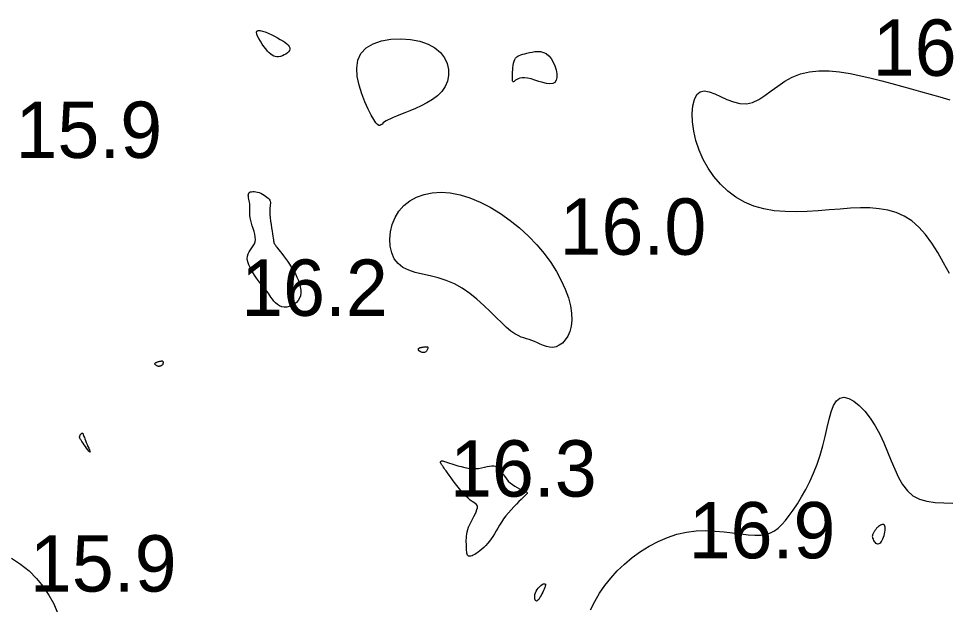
# Model space of a CAD drawing. Extents: x 3040093 to 3056816, y 408076 to 509144.
# Drawn here: x 3045513.5 to 3045596, y 434343.4 to 434395.4 of the extents above; entities that cross this region are included whole.
import ezdxf

# ---------------------------------------------------------------- set-up
doc = ezdxf.new("R2010")
doc.units = 0
doc.layers.add('V-CHAN-CONT-EL17', color=7, linetype='Continuous')
doc.layers.add('V-TOPO-SOUN-0610', color=7, linetype='Continuous')

msp = doc.modelspace()

# ---------------------------------------------------------------- linework, layer by layer
at = {"layer": 'V-CHAN-CONT-EL17'}
for points in [[(3045534.704, 434394.312), (3045534.867, 434394.31), (3045535.076, 434394.265), (3045535.321, 434394.183), (3045535.589, 434394.074), (3045535.868, 434393.946), (3045536.149, 434393.807), (3045536.418, 434393.664), (3045536.666, 434393.525), (3045536.889, 434393.391), (3045537.083, 434393.261), (3045537.246, 434393.134), (3045537.374, 434393.01), (3045537.464, 434392.889), (3045537.515, 434392.77), (3045537.521, 434392.652), (3045537.483, 434392.536), (3045537.405, 434392.423), (3045537.296, 434392.317), (3045537.161, 434392.221), (3045537.009, 434392.136), (3045536.847, 434392.067), (3045536.681, 434392.016), (3045536.52, 434391.986), (3045536.368, 434391.98), (3045536.224, 434391.998), (3045536.086, 434392.041), (3045535.951, 434392.111), (3045535.816, 434392.208), (3045535.677, 434392.332), (3045535.532, 434392.486), (3045535.379, 434392.669), (3045535.216, 434392.881), (3045535.051, 434393.111), (3045534.895, 434393.35), (3045534.758, 434393.585), (3045534.65, 434393.804), (3045534.58, 434393.998), (3045534.56, 434394.154), (3045534.599, 434394.262)], [(3045544.269, 434392.762), (3045544.898, 434393.134), (3045545.651, 434393.391), (3045546.484, 434393.539), (3045547.355, 434393.58), (3045548.223, 434393.519), (3045549.044, 434393.36), (3045549.776, 434393.106), (3045550.385, 434392.765), (3045550.866, 434392.35), (3045551.224, 434391.881), (3045551.461, 434391.374), (3045551.583, 434390.848), (3045551.592, 434390.321), (3045551.492, 434389.809), (3045551.288, 434389.331), (3045550.985, 434388.9), (3045550.601, 434388.518), (3045550.155, 434388.179), (3045549.669, 434387.88), (3045549.162, 434387.618), (3045548.654, 434387.387), (3045548.165, 434387.186), (3045547.716, 434387.01), (3045547.321, 434386.855), (3045546.981, 434386.718), (3045546.691, 434386.596), (3045546.444, 434386.486), (3045546.236, 434386.385), (3045546.062, 434386.289), (3045545.917, 434386.196), (3045545.796, 434386.102), (3045545.692, 434386.009), (3045545.598, 434385.93), (3045545.504, 434385.885), (3045545.403, 434385.891), (3045545.283, 434385.966), (3045545.138, 434386.131), (3045544.956, 434386.401), (3045544.731, 434386.797), (3045544.459, 434387.328), (3045544.167, 434387.969), (3045543.886, 434388.687), (3045543.65, 434389.449), (3045543.491, 434390.222), (3045543.442, 434390.972), (3045543.536, 434391.666), (3045543.805, 434392.272)], [(3045557.354, 434389.768), (3045557.318, 434389.766), (3045557.292, 434389.787), (3045557.276, 434389.832), (3045557.266, 434389.901), (3045557.262, 434389.994), (3045557.262, 434390.113), (3045557.265, 434390.257), (3045557.269, 434390.426), (3045557.275, 434390.613), (3045557.286, 434390.812), (3045557.303, 434391.016), (3045557.328, 434391.218), (3045557.363, 434391.411), (3045557.41, 434391.586), (3045557.47, 434391.739), (3045557.544, 434391.863), (3045557.635, 434391.961), (3045557.742, 434392.039), (3045557.866, 434392.101), (3045558.009, 434392.152), (3045558.17, 434392.197), (3045558.35, 434392.241), (3045558.551, 434392.289), (3045558.771, 434392.343), (3045559.008, 434392.395), (3045559.255, 434392.434), (3045559.509, 434392.451), (3045559.763, 434392.433), (3045560.014, 434392.371), (3045560.256, 434392.254), (3045560.484, 434392.072), (3045560.693, 434391.818), (3045560.875, 434391.509), (3045561.025, 434391.167), (3045561.135, 434390.812), (3045561.197, 434390.467), (3045561.205, 434390.152), (3045561.151, 434389.89), (3045561.028, 434389.701), (3045560.833, 434389.6), (3045560.577, 434389.576), (3045560.275, 434389.613), (3045559.942, 434389.692), (3045559.593, 434389.796), (3045559.244, 434389.907), (3045558.909, 434390.008), (3045558.603, 434390.082), (3045558.338, 434390.115), (3045558.113, 434390.111), (3045557.926, 434390.08), (3045557.771, 434390.028), (3045557.645, 434389.965), (3045557.544, 434389.9), (3045557.464, 434389.839), (3045557.402, 434389.793)], [(3045534.743, 434372.083), (3045534.56, 434372.335), (3045534.372, 434372.613), (3045534.189, 434372.906), (3045534.023, 434373.206), (3045533.886, 434373.502), (3045533.788, 434373.785), (3045533.741, 434374.046), (3045533.753, 434374.278), (3045533.813, 434374.485), (3045533.909, 434374.673), (3045534.027, 434374.849), (3045534.152, 434375.02), (3045534.271, 434375.191), (3045534.371, 434375.37), (3045534.437, 434375.563), (3045534.46, 434375.774), (3045534.446, 434376.001), (3045534.401, 434376.241), (3045534.336, 434376.487), (3045534.258, 434376.737), (3045534.178, 434376.985), (3045534.102, 434377.228), (3045534.04, 434377.46), (3045533.999, 434377.678), (3045533.976, 434377.884), (3045533.967, 434378.077), (3045533.967, 434378.26), (3045533.971, 434378.434), (3045533.976, 434378.6), (3045533.976, 434378.76), (3045533.968, 434378.914), (3045533.947, 434379.065), (3045533.919, 434379.209), (3045533.887, 434379.347), (3045533.857, 434379.476), (3045533.835, 434379.595), (3045533.825, 434379.702), (3045533.832, 434379.795), (3045533.862, 434379.873), (3045533.919, 434379.934), (3045534, 434379.979), (3045534.101, 434380.008), (3045534.22, 434380.021), (3045534.352, 434380.019), (3045534.494, 434380.001), (3045534.643, 434379.969), (3045534.795, 434379.923), (3045534.946, 434379.863), (3045535.094, 434379.791), (3045535.236, 434379.71), (3045535.367, 434379.621), (3045535.485, 434379.528), (3045535.588, 434379.432), (3045535.671, 434379.337), (3045535.732, 434379.243), (3045535.768, 434379.152), (3045535.785, 434379.06), (3045535.786, 434378.962), (3045535.776, 434378.853), (3045535.762, 434378.726), (3045535.747, 434378.578), (3045535.736, 434378.401), (3045535.736, 434378.192), (3045535.749, 434377.947), (3045535.774, 434377.674), (3045535.808, 434377.384), (3045535.848, 434377.087), (3045535.891, 434376.795), (3045535.934, 434376.517), (3045535.974, 434376.264), (3045536.009, 434376.047), (3045536.036, 434375.874), (3045536.057, 434375.74), (3045536.072, 434375.64), (3045536.084, 434375.566), (3045536.094, 434375.512), (3045536.105, 434375.472), (3045536.118, 434375.438), (3045536.135, 434375.405), (3045536.157, 434375.366), (3045536.187, 434375.318), (3045536.227, 434375.258), (3045536.278, 434375.184), (3045536.344, 434375.094), (3045536.426, 434374.984), (3045536.527, 434374.852), (3045536.647, 434374.696), (3045536.79, 434374.513), (3045536.95, 434374.306), (3045537.122, 434374.078), (3045537.302, 434373.831), (3045537.485, 434373.569), (3045537.666, 434373.294), (3045537.84, 434373.01), (3045538.001, 434372.72), (3045538.146, 434372.426), (3045538.269, 434372.131), (3045538.369, 434371.84), (3045538.44, 434371.555), (3045538.48, 434371.28), (3045538.484, 434371.018), (3045538.449, 434370.773), (3045538.372, 434370.547), (3045538.251, 434370.344), (3045538.092, 434370.167), (3045537.903, 434370.019), (3045537.692, 434369.902), (3045537.467, 434369.819), (3045537.236, 434369.773), (3045537.008, 434369.766), (3045536.791, 434369.802), (3045536.591, 434369.881), (3045536.408, 434369.996), (3045536.243, 434370.138), (3045536.094, 434370.298), (3045535.96, 434370.467), (3045535.841, 434370.636), (3045535.735, 434370.795), (3045535.643, 434370.937), (3045535.562, 434371.055), (3045535.488, 434371.154), (3045535.417, 434371.244), (3045535.342, 434371.333), (3045535.258, 434371.431), (3045535.162, 434371.546), (3045535.047, 434371.688), (3045534.908, 434371.865)], [(3045551.393, 434372.133), (3045550.675, 434372.357), (3045549.967, 434372.533), (3045549.284, 434372.687), (3045548.642, 434372.847), (3045548.055, 434373.038), (3045547.54, 434373.287), (3045547.11, 434373.621), (3045546.778, 434374.058), (3045546.546, 434374.582), (3045546.413, 434375.172), (3045546.377, 434375.803), (3045546.439, 434376.453), (3045546.597, 434377.098), (3045546.849, 434377.715), (3045547.195, 434378.28), (3045547.633, 434378.774), (3045548.155, 434379.189), (3045548.754, 434379.519), (3045549.421, 434379.76), (3045550.148, 434379.908), (3045550.927, 434379.957), (3045551.75, 434379.902), (3045552.608, 434379.739), (3045553.493, 434379.466), (3045554.393, 434379.091), (3045555.296, 434378.624), (3045556.188, 434378.077), (3045557.058, 434377.461), (3045557.894, 434376.786), (3045558.682, 434376.064), (3045559.411, 434375.305), (3045560.07, 434374.521), (3045560.655, 434373.722), (3045561.164, 434372.919), (3045561.596, 434372.123), (3045561.948, 434371.345), (3045562.219, 434370.594), (3045562.407, 434369.883), (3045562.509, 434369.222), (3045562.527, 434368.619), (3045562.468, 434368.079), (3045562.344, 434367.603), (3045562.166, 434367.194), (3045561.945, 434366.852), (3045561.692, 434366.579), (3045561.417, 434366.378), (3045561.132, 434366.25), (3045560.845, 434366.195), (3045560.561, 434366.201), (3045560.28, 434366.257), (3045560.004, 434366.348), (3045559.734, 434366.462), (3045559.472, 434366.586), (3045559.219, 434366.706), (3045558.975, 434366.811), (3045558.743, 434366.89), (3045558.513, 434366.956), (3045558.279, 434367.024), (3045558.032, 434367.111), (3045557.763, 434367.231), (3045557.465, 434367.4), (3045557.129, 434367.635), (3045556.747, 434367.951), (3045556.312, 434368.357), (3045555.827, 434368.836), (3045555.296, 434369.362), (3045554.724, 434369.91), (3045554.115, 434370.456), (3045553.472, 434370.976), (3045552.801, 434371.443), (3045552.106, 434371.835)], [(3045548.943, 434365.924), (3045548.933, 434365.942), (3045548.925, 434365.961), (3045548.919, 434365.981), (3045548.915, 434366.001), (3045548.914, 434366.021), (3045548.917, 434366.042), (3045548.923, 434366.061), (3045548.933, 434366.08), (3045548.947, 434366.097), (3045548.964, 434366.114), (3045548.983, 434366.129), (3045549.005, 434366.142), (3045549.028, 434366.154), (3045549.052, 434366.165), (3045549.077, 434366.173), (3045549.102, 434366.18), (3045549.127, 434366.186), (3045549.154, 434366.19), (3045549.184, 434366.194), (3045549.218, 434366.199), (3045549.255, 434366.204), (3045549.298, 434366.211), (3045549.347, 434366.219), (3045549.403, 434366.23), (3045549.462, 434366.24), (3045549.523, 434366.249), (3045549.582, 434366.254), (3045549.637, 434366.254), (3045549.684, 434366.245), (3045549.722, 434366.227), (3045549.746, 434366.196), (3045549.754, 434366.153), (3045549.749, 434366.099), (3045549.731, 434366.039), (3045549.703, 434365.975), (3045549.666, 434365.912), (3045549.622, 434365.853), (3045549.574, 434365.802), (3045549.521, 434365.762), (3045549.467, 434365.737), (3045549.413, 434365.725), (3045549.359, 434365.723), (3045549.306, 434365.73), (3045549.255, 434365.743), (3045549.207, 434365.76), (3045549.163, 434365.779), (3045549.123, 434365.798), (3045549.089, 434365.815), (3045549.059, 434365.829), (3045549.034, 434365.843), (3045549.013, 434365.855), (3045548.995, 434365.867), (3045548.98, 434365.88), (3045548.966, 434365.893), (3045548.954, 434365.907)], [(3045525.758, 434364.538), (3045525.714, 434364.559), (3045525.671, 434364.584), (3045525.63, 434364.611), (3045525.595, 434364.641), (3045525.566, 434364.671), (3045525.547, 434364.702), (3045525.541, 434364.732), (3045525.547, 434364.761), (3045525.566, 434364.788), (3045525.594, 434364.813), (3045525.63, 434364.836), (3045525.672, 434364.858), (3045525.718, 434364.878), (3045525.764, 434364.895), (3045525.81, 434364.911), (3045525.853, 434364.925), (3045525.893, 434364.937), (3045525.931, 434364.948), (3045525.966, 434364.957), (3045525.999, 434364.964), (3045526.029, 434364.97), (3045526.058, 434364.975), (3045526.085, 434364.979), (3045526.11, 434364.983), (3045526.134, 434364.985), (3045526.156, 434364.986), (3045526.175, 434364.986), (3045526.193, 434364.984), (3045526.209, 434364.98), (3045526.223, 434364.975), (3045526.234, 434364.968), (3045526.243, 434364.959), (3045526.25, 434364.947), (3045526.255, 434364.934), (3045526.258, 434364.919), (3045526.26, 434364.902), (3045526.262, 434364.884), (3045526.262, 434364.864), (3045526.262, 434364.843), (3045526.262, 434364.821), (3045526.261, 434364.798), (3045526.259, 434364.774), (3045526.255, 434364.751), (3045526.25, 434364.727), (3045526.243, 434364.704), (3045526.233, 434364.682), (3045526.22, 434364.661), (3045526.204, 434364.641), (3045526.185, 434364.623), (3045526.164, 434364.606), (3045526.141, 434364.59), (3045526.116, 434364.576), (3045526.091, 434364.562), (3045526.065, 434364.55), (3045526.039, 434364.538), (3045526.014, 434364.527), (3045525.988, 434364.518), (3045525.962, 434364.51), (3045525.934, 434364.505), (3045525.905, 434364.503), (3045525.873, 434364.505), (3045525.838, 434364.511), (3045525.8, 434364.522)], [(3045518.863, 434358.237), (3045518.866, 434358.257), (3045518.87, 434358.278), (3045518.876, 434358.302), (3045518.884, 434358.329), (3045518.895, 434358.357), (3045518.908, 434358.387), (3045518.925, 434358.419), (3045518.945, 434358.453), (3045518.968, 434358.487), (3045518.993, 434358.518), (3045519.019, 434358.546), (3045519.046, 434358.567), (3045519.073, 434358.579), (3045519.099, 434358.582), (3045519.123, 434358.572), (3045519.145, 434358.548), (3045519.167, 434358.509), (3045519.19, 434358.454), (3045519.216, 434358.382), (3045519.247, 434358.294), (3045519.285, 434358.187), (3045519.332, 434358.062), (3045519.388, 434357.917), (3045519.456, 434357.754), (3045519.53, 434357.581), (3045519.605, 434357.407), (3045519.674, 434357.243), (3045519.733, 434357.098), (3045519.775, 434356.983), (3045519.794, 434356.907), (3045519.785, 434356.88), (3045519.745, 434356.908), (3045519.677, 434356.985), (3045519.588, 434357.098), (3045519.486, 434357.237), (3045519.377, 434357.392), (3045519.267, 434357.55), (3045519.164, 434357.702), (3045519.074, 434357.836), (3045519.003, 434357.944), (3045518.949, 434358.027), (3045518.911, 434358.089), (3045518.885, 434358.133), (3045518.869, 434358.165), (3045518.862, 434358.187), (3045518.86, 434358.204), (3045518.861, 434358.22)], [(3045553.251, 434347.839), (3045553.227, 434347.932), (3045553.21, 434348.04), (3045553.197, 434348.163), (3045553.188, 434348.296), (3045553.182, 434348.44), (3045553.177, 434348.591), (3045553.173, 434348.748), (3045553.169, 434348.91), (3045553.167, 434349.077), (3045553.17, 434349.25), (3045553.182, 434349.43), (3045553.205, 434349.618), (3045553.243, 434349.816), (3045553.298, 434350.024), (3045553.374, 434350.243), (3045553.471, 434350.474), (3045553.584, 434350.711), (3045553.705, 434350.949), (3045553.826, 434351.182), (3045553.94, 434351.404), (3045554.037, 434351.61), (3045554.111, 434351.792), (3045554.154, 434351.946), (3045554.16, 434352.068), (3045554.129, 434352.166), (3045554.064, 434352.249), (3045553.968, 434352.327), (3045553.844, 434352.412), (3045553.694, 434352.512), (3045553.521, 434352.637), (3045553.328, 434352.799), (3045553.118, 434353.002), (3045552.897, 434353.241), (3045552.669, 434353.505), (3045552.44, 434353.785), (3045552.217, 434354.069), (3045552.005, 434354.348), (3045551.81, 434354.611), (3045551.637, 434354.848), (3045551.491, 434355.052), (3045551.369, 434355.223), (3045551.27, 434355.366), (3045551.19, 434355.482), (3045551.126, 434355.578), (3045551.076, 434355.655), (3045551.035, 434355.717), (3045551.002, 434355.768), (3045550.973, 434355.811), (3045550.948, 434355.848), (3045550.927, 434355.879), (3045550.91, 434355.905), (3045550.897, 434355.929), (3045550.888, 434355.95), (3045550.882, 434355.97), (3045550.881, 434355.989), (3045550.882, 434356.009), (3045550.887, 434356.03), (3045550.896, 434356.05), (3045550.907, 434356.069), (3045550.922, 434356.086), (3045550.94, 434356.101), (3045550.96, 434356.113), (3045550.983, 434356.121), (3045551.01, 434356.125), (3045551.044, 434356.123), (3045551.09, 434356.115), (3045551.153, 434356.099), (3045551.237, 434356.073), (3045551.349, 434356.037), (3045551.492, 434355.99), (3045551.671, 434355.93), (3045551.889, 434355.856), (3045552.141, 434355.775), (3045552.42, 434355.69), (3045552.718, 434355.61), (3045553.028, 434355.538), (3045553.344, 434355.481), (3045553.657, 434355.445), (3045553.96, 434355.436), (3045554.248, 434355.456), (3045554.519, 434355.499), (3045554.773, 434355.553), (3045555.009, 434355.61), (3045555.229, 434355.658), (3045555.43, 434355.688), (3045555.614, 434355.689), (3045555.781, 434355.652), (3045555.93, 434355.569), (3045556.066, 434355.446), (3045556.194, 434355.291), (3045556.319, 434355.112), (3045556.446, 434354.919), (3045556.58, 434354.719), (3045556.726, 434354.521), (3045556.888, 434354.333), (3045557.07, 434354.163), (3045557.267, 434354.01), (3045557.472, 434353.875), (3045557.677, 434353.757), (3045557.875, 434353.653), (3045558.059, 434353.564), (3045558.223, 434353.489), (3045558.359, 434353.427), (3045558.46, 434353.376), (3045558.527, 434353.331), (3045558.559, 434353.287), (3045558.557, 434353.237), (3045558.52, 434353.175), (3045558.449, 434353.096), (3045558.344, 434352.994), (3045558.205, 434352.863), (3045558.033, 434352.699), (3045557.835, 434352.505), (3045557.617, 434352.285), (3045557.386, 434352.045), (3045557.149, 434351.788), (3045556.914, 434351.521), (3045556.687, 434351.246), (3045556.476, 434350.97), (3045556.285, 434350.696), (3045556.113, 434350.427), (3045555.954, 434350.163), (3045555.805, 434349.907), (3045555.662, 434349.659), (3045555.52, 434349.421), (3045555.376, 434349.195), (3045555.224, 434348.982), (3045555.062, 434348.783), (3045554.893, 434348.6), (3045554.72, 434348.431), (3045554.546, 434348.278), (3045554.374, 434348.141), (3045554.209, 434348.02), (3045554.054, 434347.915), (3045553.912, 434347.827), (3045553.786, 434347.756), (3045553.675, 434347.703), (3045553.579, 434347.667), (3045553.497, 434347.65), (3045553.427, 434347.65), (3045553.368, 434347.669), (3045553.32, 434347.707), (3045553.282, 434347.763)], [(3045589.707, 434348.752), (3045589.784, 434348.775), (3045589.858, 434348.822), (3045589.931, 434348.89), (3045590.001, 434348.977), (3045590.066, 434349.083), (3045590.126, 434349.205), (3045590.18, 434349.342), (3045590.227, 434349.491), (3045590.266, 434349.647), (3045590.295, 434349.804), (3045590.313, 434349.958), (3045590.32, 434350.101), (3045590.314, 434350.229), (3045590.294, 434350.335), (3045590.259, 434350.414), (3045590.208, 434350.463), (3045590.143, 434350.482), (3045590.07, 434350.478), (3045589.99, 434350.454), (3045589.907, 434350.415), (3045589.825, 434350.365), (3045589.747, 434350.309), (3045589.677, 434350.251), (3045589.617, 434350.194), (3045589.566, 434350.139), (3045589.522, 434350.086), (3045589.485, 434350.034), (3045589.451, 434349.983), (3045589.42, 434349.934), (3045589.389, 434349.884), (3045589.358, 434349.835), (3045589.324, 434349.786), (3045589.289, 434349.735), (3045589.256, 434349.682), (3045589.227, 434349.625), (3045589.204, 434349.564), (3045589.189, 434349.497), (3045589.184, 434349.424), (3045589.192, 434349.343), (3045589.213, 434349.254), (3045589.248, 434349.16), (3045589.294, 434349.067), (3045589.35, 434348.977), (3045589.413, 434348.897), (3045589.482, 434348.83), (3045589.555, 434348.781), (3045589.631, 434348.754)], [(3045559.309, 434343.727), (3045559.272, 434343.797), (3045559.246, 434343.892), (3045559.233, 434344.007), (3045559.235, 434344.136), (3045559.255, 434344.276), (3045559.295, 434344.421), (3045559.358, 434344.566), (3045559.443, 434344.706), (3045559.546, 434344.838), (3045559.659, 434344.957), (3045559.777, 434345.059), (3045559.891, 434345.14), (3045559.995, 434345.197), (3045560.082, 434345.224), (3045560.145, 434345.218), (3045560.179, 434345.177), (3045560.185, 434345.103), (3045560.169, 434345.004), (3045560.133, 434344.885), (3045560.082, 434344.75), (3045560.02, 434344.606), (3045559.95, 434344.458), (3045559.876, 434344.312), (3045559.802, 434344.172), (3045559.729, 434344.044), (3045559.658, 434343.929), (3045559.589, 434343.832), (3045559.524, 434343.756), (3045559.462, 434343.704), (3045559.406, 434343.68), (3045559.354, 434343.687)]]:
    msp.add_lwpolyline(points, close=True, dxfattribs=at)
for points in [[(3045596.028, 434372.74), (3045595.514, 434373.696), (3045594.991, 434374.601), (3045594.452, 434375.44), (3045593.892, 434376.196), (3045593.303, 434376.857), (3045592.68, 434377.406), (3045592.018, 434377.833), (3045591.315, 434378.149), (3045590.574, 434378.366), (3045589.795, 434378.498), (3045588.979, 434378.561), (3045588.127, 434378.567), (3045587.24, 434378.531), (3045586.319, 434378.467), (3045585.368, 434378.388), (3045584.394, 434378.311), (3045583.408, 434378.25), (3045582.422, 434378.22), (3045581.445, 434378.237), (3045580.489, 434378.316), (3045579.564, 434378.471), (3045578.681, 434378.719), (3045577.849, 434379.071), (3045577.074, 434379.519), (3045576.358, 434380.055), (3045575.706, 434380.668), (3045575.123, 434381.349), (3045574.611, 434382.086), (3045574.174, 434382.871), (3045573.817, 434383.692), (3045573.543, 434384.537), (3045573.351, 434385.382), (3045573.241, 434386.198), (3045573.213, 434386.957), (3045573.266, 434387.632), (3045573.4, 434388.196), (3045573.613, 434388.619), (3045573.906, 434388.875), (3045574.275, 434388.948), (3045574.711, 434388.871), (3045575.2, 434388.689), (3045575.731, 434388.448), (3045576.29, 434388.193), (3045576.866, 434387.968), (3045577.445, 434387.82), (3045578.016, 434387.794), (3045578.57, 434387.921), (3045579.113, 434388.179), (3045579.659, 434388.532), (3045580.217, 434388.945), (3045580.8, 434389.381), (3045581.419, 434389.805), (3045582.085, 434390.181), (3045582.811, 434390.473), (3045583.602, 434390.655), (3045584.451, 434390.731), (3045585.344, 434390.719), (3045586.268, 434390.632), (3045587.21, 434390.486), (3045588.158, 434390.297), (3045589.098, 434390.078), (3045590.017, 434389.846), (3045590.905, 434389.613), (3045591.77, 434389.379), (3045592.621, 434389.145), (3045593.467, 434388.907), (3045594.318, 434388.666), (3045595.183, 434388.419), (3045596.074, 434388.165)], [(3045564.18, 434342.898), (3045564.564, 434343.649), (3045564.989, 434344.367), (3045565.461, 434345.056), (3045565.983, 434345.717), (3045566.56, 434346.352), (3045567.194, 434346.961), (3045567.881, 434347.537), (3045568.613, 434348.072), (3045569.383, 434348.555), (3045570.184, 434348.979), (3045571.009, 434349.335), (3045571.851, 434349.613), (3045572.702, 434349.804), (3045573.556, 434349.905), (3045574.402, 434349.929), (3045575.23, 434349.895), (3045576.031, 434349.822), (3045576.795, 434349.729), (3045577.512, 434349.635), (3045578.172, 434349.558), (3045578.764, 434349.518), (3045579.284, 434349.53), (3045579.739, 434349.598), (3045580.142, 434349.724), (3045580.505, 434349.909), (3045580.842, 434350.155), (3045581.165, 434350.461), (3045581.486, 434350.83), (3045581.819, 434351.264), (3045582.171, 434351.761), (3045582.538, 434352.318), (3045582.911, 434352.93), (3045583.282, 434353.592), (3045583.641, 434354.298), (3045583.981, 434355.044), (3045584.291, 434355.824), (3045584.564, 434356.632), (3045584.795, 434357.461), (3045584.994, 434358.287), (3045585.175, 434359.084), (3045585.352, 434359.825), (3045585.539, 434360.482), (3045585.752, 434361.031), (3045586.003, 434361.444), (3045586.306, 434361.694), (3045586.673, 434361.763), (3045587.091, 434361.662), (3045587.546, 434361.408), (3045588.023, 434361.02), (3045588.507, 434360.518), (3045588.983, 434359.918), (3045589.435, 434359.241), (3045589.849, 434358.504), (3045590.214, 434357.726), (3045590.544, 434356.93), (3045590.857, 434356.138), (3045591.17, 434355.372), (3045591.502, 434354.656), (3045591.87, 434354.011), (3045592.292, 434353.462), (3045592.787, 434353.029), (3045593.367, 434352.728), (3045594.025, 434352.539), (3045594.747, 434352.436), (3045595.521, 434352.391), (3045596.335, 434352.378)], [(3045512.815, 434347.492), (3045513.633, 434346.952), (3045514.383, 434346.349), (3045515.052, 434345.681), (3045515.639, 434344.962), (3045516.143, 434344.205), (3045516.564, 434343.427), (3045516.902, 434342.642)]]:
    msp.add_lwpolyline(points, dxfattribs=at)

# ---------------------------------------------------------------- texts
at = {"layer": 'V-TOPO-SOUN-0610'}
for s, p in [('16.5 ', (3045589.223, 434390.29)), ('15.9 ', (3045513.173, 434383)), ('16.0 ', (3045561.443, 434374.41)), ('16.2 ', (3045533.193, 434368.99)), ('16.3 ', (3045551.723, 434352.95)), ('16.9 ', (3045572.893, 434347.47)), ('15.9 ', (3045514.453, 434344.52))]:
    msp.add_text(s, height=5, dxfattribs=at).set_placement(p)

doc.saveas('drawing.dxf')
